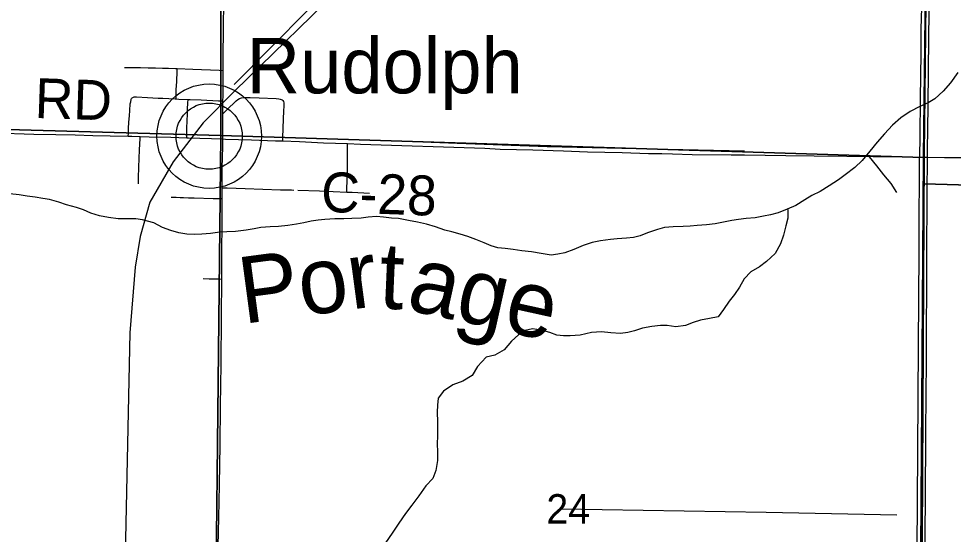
# Model space of a CAD drawing. Extents: x 0 to 39.4, y 0 to 22.
# Drawn here: x 4.106 to 5.438, y 17.856 to 18.59 of the extents above; entities that cross this region are included whole.
import ezdxf

# ---------------------------------------------------------------- set-up
doc = ezdxf.new("R2010")
doc.units = 0
for name, color, linetype in [('GM_X_County_Road', 7, 'Continuous'), ('GM_X_County_Road_Text', 7, 'Continuous'), ('GM_X_Interstate_Route', 7, 'Continuous'), ('GM_X_Major_River', 7, 'Continuous'), ('GM_X_Major_River_Text', 7, 'Continuous'), ('GM_X_Minor_River', 7, 'Continuous'), ('GM_X_Rail_Line', 7, 'Continuous'), ('GM_X_Section', 7, 'Continuous'), ('GM_X_Section_Text', 7, 'Continuous'), ('GM_X_State_Route', 7, 'Continuous'), ('GM_X_Township_Road', 7, 'Continuous'), ('GM_X_Unincorporated', 7, 'Continuous'), ('GM_X_Unincorporated_Location', 7, 'Continuous'), ('GM_X_Unincorporated_Text', 7, 'Continuous')]:
    doc.layers.add(name, color=color, linetype=linetype)

msp = doc.modelspace()

# ---------------------------------------------------------------- linework, layer by layer
at = {"layer": 'GM_X_County_Road'}
for p, q in [((5.3898, 18.3932), (5.3952, 18.3932)), ((5.3952, 18.3932), (5.4008, 18.3931))]:
    msp.add_line(p, q, dxfattribs=at)
for points in [[(3.3797, 18.4462), (3.4197, 18.4448), (3.4663, 18.4434), (3.5378, 18.442), (3.5968, 18.4411), (3.6527, 18.4402), (3.6683, 18.4398), (3.6869, 18.4394), (3.7086, 18.439), (3.7117, 18.4389), (3.7211, 18.4386), (3.7646, 18.4375), (3.864, 18.4344), (3.9292, 18.4325), (3.982, 18.4306), (4.0721, 18.4275), (4.128, 18.4259), (4.1591, 18.4251), (4.187, 18.4246), (4.2119, 18.424), (4.2366, 18.4232), (4.2624, 18.4228)], [(4.2624, 18.4228), (4.2674, 18.4227), (4.2796, 18.4224)], [(4.2796, 18.4224), (4.2922, 18.4221), (4.3233, 18.4213), (4.3457, 18.4205)], [(4.3457, 18.4205), (4.3481, 18.4204), (4.3972, 18.4189)], [(4.3972, 18.4189), (4.4009, 18.4188), (4.4382, 18.4177), (4.4723, 18.4164), (4.4821, 18.4161)], [(4.4821, 18.4161), (4.5065, 18.4153), (4.5406, 18.4136), (4.5748, 18.4123)], [(4.5748, 18.4123), (4.5934, 18.4115), (4.7704, 18.4056), (4.7921, 18.4045), (4.8388, 18.4033), (4.8822, 18.4018), (4.9164, 18.4007), (4.9412, 18.4), (4.9661, 18.3994), (5.0034, 18.3983), (5.0227, 18.398), (5.0376, 18.3977), (5.0655, 18.3969), (5.1214, 18.3964), (5.1401, 18.3964), (5.1991, 18.3955), (5.2395, 18.3948), (5.2861, 18.3944), (5.3234, 18.3938), (5.37, 18.3933), (5.3898, 18.3932)], [(5.4008, 18.3931), (5.4252, 18.3927), (5.4594, 18.3926)]]:
    msp.add_lwpolyline(points, dxfattribs=at)
at = {"layer": 'GM_X_Interstate_Route'}
for points in [[(5.3867, 16.794), (5.3887, 17.3876), (5.3908, 17.7563), (5.3909, 17.7629), (5.395, 18.3937), (5.4055, 19.2651), (5.4066, 19.3573), (5.4067, 19.4006), (5.4136, 19.9268)], [(5.4136, 19.9268), (5.4067, 19.4006), (5.4066, 19.3573), (5.4055, 19.2651), (5.395, 18.3937), (5.3909, 17.7629), (5.3908, 17.7563), (5.3887, 17.3876), (5.3867, 16.794)]]:
    msp.add_lwpolyline(points, dxfattribs=at)
at = {"layer": 'GM_X_Major_River'}
for points in [[(5.444, 18.5134), (5.4337, 18.499), (5.4234, 18.4869), (5.4112, 18.4763), (5.4017, 18.4702), (5.3899, 18.4653), (5.3763, 18.4581), (5.363, 18.4491), (5.3512, 18.4385), (5.3397, 18.4263), (5.3291, 18.4142), (5.3188, 18.4017), (5.3078, 18.3881), (5.2975, 18.3782), (5.2834, 18.368), (5.2739, 18.3608), (5.261, 18.3521), (5.2481, 18.3442), (5.2359, 18.3385), (5.2264, 18.3321), (5.2135, 18.3241), (5.2009, 18.3189), (5.1884, 18.3139), (5.1774, 18.3109), (5.1671, 18.3087), (5.1554, 18.3064), (5.1428, 18.3057), (5.1315, 18.3042), (5.122, 18.3027), (5.1079, 18.2998), (5.0984, 18.2979), (5.0859, 18.2968), (5.073, 18.2957), (5.0628, 18.2949), (5.0529, 18.2942), (5.0388, 18.2935), (5.0263, 18.2928), (5.0165, 18.2901), (5.002, 18.2852), (4.9918, 18.2807), (4.9819, 18.2785), (4.972, 18.2777), (4.9587, 18.2766), (4.9493, 18.2759), (4.9352, 18.274), (4.9231, 18.2714), (4.9105, 18.2669), (4.8972, 18.2612), (4.8843, 18.2567), (4.8744, 18.2548), (4.865, 18.2534), (4.8505, 18.2557), (4.8369, 18.258), (4.8232, 18.2596), (4.8107, 18.2615), (4.7993, 18.2627), (4.7891, 18.2638), (4.7796, 18.2665), (4.7694, 18.2707), (4.7577, 18.2757), (4.7459, 18.2799), (4.7353, 18.2834), (4.7235, 18.2864), (4.7133, 18.2891), (4.7, 18.2937), (4.6872, 18.2976), (4.6743, 18.3003), (4.6617, 18.3026), (4.6473, 18.3057), (4.6375, 18.3061), (4.6261, 18.3076), (4.6159, 18.3084), (4.6041, 18.3077), (4.5942, 18.3062), (4.5809, 18.3055), (4.5696, 18.3051), (4.5567, 18.3052), (4.5426, 18.3044), (4.5331, 18.3033), (4.5229, 18.3018), (4.5126, 18.2996), (4.502, 18.2973), (4.4899, 18.2955), (4.4766, 18.2944), (4.4648, 18.2937), (4.4515, 18.2926), (4.4417, 18.2911), (4.4303, 18.2892), (4.4151, 18.2873), (4.403, 18.2866), (4.3931, 18.2859), (4.3798, 18.2844), (4.3673, 18.2833)], [(4.3673, 18.2833), (4.3563, 18.2826), (4.346, 18.2834), (4.3347, 18.2853), (4.3229, 18.2884), (4.3112, 18.2926), (4.2987, 18.2995), (4.2827, 18.3037), (4.2733, 18.3049), (4.2611, 18.3049), (4.2482, 18.3053), (4.2342, 18.3069), (4.2213, 18.3096), (4.2092, 18.3134), (4.1986, 18.318), (4.1887, 18.3214), (4.1743, 18.3253), (4.1633, 18.3287), (4.1504, 18.3326), (4.1406, 18.3341), (4.1299, 18.336), (4.1182, 18.3376), (4.1068, 18.3392), (4.0939, 18.3407)]]:
    msp.add_lwpolyline(points, dxfattribs=at)
at = {"layer": 'GM_X_Minor_River'}
for points in [[(5.1261, 18.645), (4.5703, 18.6557), (4.4131, 18.4963)], [(4.6325, 18.4166), (4.7308, 18.4129), (4.859, 18.4084), (5.0081, 18.4049), (5.1401, 18.4018)], [(5.3176, 18.3933), (5.3282, 18.3804), (5.3384, 18.3678), (5.3486, 18.3556), (5.3569, 18.3427)], [(5.2021, 18.3185), (5.202, 18.3063), (5.199, 18.2953), (5.1959, 18.282), (5.1913, 18.2695), (5.1837, 18.2558), (5.1715, 18.2441), (5.1616, 18.2369), (5.1491, 18.2294), (5.1399, 18.2195), (5.1331, 18.2077), (5.1258, 18.1975), (5.1182, 18.1877), (5.1102, 18.1759), (5.1026, 18.1657), (5.0904, 18.163), (5.0775, 18.1608), (5.0669, 18.1574), (5.0562, 18.1533), (5.0426, 18.1514), (5.0301, 18.153), (5.0206, 18.153), (5.0081, 18.1515), (4.9951, 18.1493), (4.9834, 18.1455), (4.9739, 18.1433), (4.9636, 18.1418), (4.9496, 18.1426), (4.9367, 18.1441), (4.9223, 18.143), (4.9063, 18.1396), (4.8919, 18.1386), (4.8824, 18.1382), (4.873, 18.1394), (4.8631, 18.1432), (4.8506, 18.1467), (4.8381, 18.1482), (4.8278, 18.146), (4.8183, 18.1399), (4.8084, 18.1308), (4.7978, 18.1183), (4.7848, 18.1108), (4.7723, 18.1078), (4.7598, 18.0949), (4.7521, 18.082), (4.7388, 18.074), (4.7248, 18.0688), (4.7115, 18.0597), (4.7038, 18.0498), (4.7027, 18.0396), (4.7026, 18.0297), (4.703, 18.016), (4.7029, 17.9951), (4.7025, 17.9853), (4.7028, 17.9723), (4.7028, 17.9606), (4.7005, 17.9465), (4.6963, 17.9351), (4.6864, 17.9249), (4.6765, 17.9105), (4.6662, 17.8972), (4.6574, 17.8851), (4.6479, 17.8714), (4.6391, 17.8589), (4.6281, 17.8422)], [(5.357, 17.8827), (5.1711, 17.8866), (4.879, 17.8913)]]:
    msp.add_lwpolyline(points, dxfattribs=at)
at = {"layer": 'GM_X_Rail_Line'}
for points in [[(4.9299, 20.9), (4.9207, 20.2492), (4.9136, 19.4102), (4.7206, 18.8553), (4.6861, 18.7801), (4.66, 18.7382), (4.6327, 18.7007), (4.4144, 18.4874), (4.369, 18.4419), (4.3263, 18.3862), (4.2933, 18.3287), (4.2793, 18.2799), (4.2724, 18.2363), (4.2649, 18.1427), (4.2497, 17.419), (4.2467, 16.9177), (4.235, 16.198), (4.2196, 15.6628), (4.2092, 15.5913), (4.1936, 15.4989), (4.1313, 15.1291), (4.1146, 15.0383)], [(5.3695, 15.387), (5.386, 16.3854), (5.3967, 18.3974), (5.4127, 19.8659), (5.4216, 20.4077), (5.4296, 20.9)]]:
    msp.add_lwpolyline(points, dxfattribs=at)
at = {"layer": 'GM_X_Section'}
for points in [[(3.377, 19.4549), (4.394, 19.4215), (4.3942, 18.4237), (3.3817, 18.4522)], [(4.394, 19.4215), (5.4059, 19.4006), (5.4065, 19.3604), (5.3953, 18.3924), (4.3942, 18.4237)], [(5.4065, 19.3604), (6.4302, 19.3208), (6.4032, 18.3261), (5.3956, 18.3552), (5.3953, 18.3924)], [(3.3817, 18.4522), (4.3942, 18.4237), (4.3832, 17.4133), (3.367, 17.4429)], [(4.3942, 18.4237), (5.3953, 18.3924), (5.3956, 18.3552), (5.3882, 17.3864), (4.3832, 17.4133)], [(5.3956, 18.3552), (6.4032, 18.3261), (6.3887, 17.3403), (5.3882, 17.3864)]]:
    msp.add_lwpolyline(points, close=True, dxfattribs=at)
at = {"layer": 'GM_X_State_Route'}
for points in [[(5.3856, 17.7703), (5.3865, 17.9009), (5.387, 17.9755), (5.388, 18.1247), (5.3889, 18.2583), (5.3892, 18.3111), (5.3896, 18.3578), (5.3897, 18.392), (5.3898, 18.3932), (5.3904, 18.423), (5.391, 18.4759), (5.3919, 18.5411), (5.3921, 18.5753), (5.3927, 18.6064)], [(5.3975, 17.8308), (5.3977, 17.8619), (5.3981, 17.9023), (5.3987, 18.0018), (5.3993, 18.1044), (5.3998, 18.2505), (5.4002, 18.3406), (5.4008, 18.3931), (5.4009, 18.4028), (5.4018, 18.465), (5.4025, 18.5178), (5.4032, 18.6018)]]:
    msp.add_lwpolyline(points, dxfattribs=at)
at = {"layer": 'GM_X_Township_Road'}
for p, q in [((4.3973, 18.4545), (4.3973, 18.4731)), ((4.3964, 18.3342), (4.3964, 18.3495))]:
    msp.add_line(p, q, dxfattribs=at)
for points in [[(4.3977, 18.5164), (4.3978, 18.5293), (4.3982, 18.582), (4.3987, 18.6094)], [(4.2573, 18.5206), (4.2667, 18.5205), (4.28, 18.5206), (4.2906, 18.5204), (4.2967, 18.5203), (4.3012, 18.5203), (4.3112, 18.52), (4.3153, 18.5198), (4.3197, 18.5197), (4.3297, 18.5192), (4.3322, 18.5191)], [(4.3307, 18.476), (4.3307, 18.48), (4.3307, 18.4829), (4.3309, 18.4889), (4.3314, 18.501), (4.332, 18.5153), (4.3322, 18.5191)], [(4.3322, 18.5191), (4.3546, 18.5182), (4.392, 18.5167), (4.3977, 18.5164)], [(4.3973, 18.4731), (4.3974, 18.4797), (4.3977, 18.5164)], [(4.2624, 18.4228), (4.2626, 18.4267), (4.2629, 18.4338), (4.2634, 18.443), (4.264, 18.4518), (4.2645, 18.4597), (4.2653, 18.4689), (4.2659, 18.472), (4.2665, 18.475), (4.2668, 18.4757), (4.2672, 18.4764), (4.2677, 18.4771), (4.2682, 18.4775), (4.269, 18.478), (4.2701, 18.4785), (4.271, 18.4787), (4.2723, 18.4789), (4.2743, 18.4788), (4.29, 18.4778), (4.3051, 18.477), (4.3118, 18.4768), (4.3203, 18.4764), (4.3294, 18.4761), (4.3307, 18.476)], [(4.3307, 18.476), (4.3346, 18.4758), (4.3476, 18.4753)], [(4.3457, 18.4205), (4.3459, 18.4275), (4.3461, 18.4346), (4.3465, 18.4444), (4.3468, 18.4546), (4.347, 18.4613), (4.3473, 18.4704), (4.3476, 18.4753)], [(4.3476, 18.4753), (4.3507, 18.4752), (4.3664, 18.4746), (4.3912, 18.4734), (4.3973, 18.4731)], [(4.3973, 18.4545), (4.4029, 18.4602), (4.4159, 18.4733), (4.4183, 18.4752), (4.421, 18.4767), (4.4239, 18.4776), (4.4269, 18.478), (4.43, 18.4781), (4.4362, 18.478), (4.4489, 18.4775), (4.473, 18.4766), (4.477, 18.4763), (4.4789, 18.4758), (4.4803, 18.4753), (4.4816, 18.4746), (4.4827, 18.4736), (4.4835, 18.4721), (4.4838, 18.4706), (4.4839, 18.4674), (4.4838, 18.4643), (4.4836, 18.4602), (4.483, 18.4456), (4.4827, 18.4357), (4.4822, 18.4192), (4.4821, 18.4161)], [(4.3972, 18.4189), (4.3972, 18.4331), (4.3972, 18.4486), (4.3973, 18.4545)], [(4.2769, 18.3552), (4.2771, 18.3637), (4.2776, 18.3788), (4.2785, 18.4034), (4.2795, 18.4196), (4.2796, 18.4224)], [(4.3964, 18.3495), (4.3964, 18.3773), (4.3971, 18.4084), (4.3971, 18.4115), (4.3972, 18.4189)], [(4.5739, 18.3433), (4.574, 18.3485), (4.5745, 18.37), (4.5746, 18.4037), (4.5747, 18.4068), (4.5748, 18.4123)], [(4.3964, 18.3495), (4.4035, 18.3492), (4.4288, 18.3482), (4.4792, 18.3466), (4.495, 18.3462), (4.4981, 18.3461)], [(4.5038, 18.3461), (4.5347, 18.345), (4.5739, 18.3433)], [(4.3235, 18.336), (4.3266, 18.3359), (4.3308, 18.3358), (4.3364, 18.3356), (4.3411, 18.3354), (4.3482, 18.3352), (4.3565, 18.3349), (4.3834, 18.3341), (4.3896, 18.3341), (4.3964, 18.3342)], [(4.3962, 18.2986), (4.3964, 18.3183), (4.3964, 18.3342)], [(4.5739, 18.3433), (4.5812, 18.343), (4.606, 18.3417)], [(4.3957, 18.2193), (4.3958, 18.2624), (4.3961, 18.2935), (4.3962, 18.2986)], [(4.3689, 18.2199), (4.3779, 18.2197), (4.3911, 18.2194), (4.3957, 18.2193)], [(4.3879, 17.4129), (4.3879, 17.4202), (4.3881, 17.5383), (4.3882, 17.5787), (4.3882, 17.6036), (4.3882, 17.6253), (4.388, 17.6657), (4.3883, 17.7248), (4.3888, 17.7496), (4.3896, 17.8025), (4.3909, 17.8584), (4.3917, 17.9019), (4.3922, 17.9268), (4.3932, 17.9827), (4.394, 18.0386), (4.3949, 18.0977), (4.3953, 18.166), (4.3957, 18.2193)]]:
    msp.add_lwpolyline(points, dxfattribs=at)
at = {"layer": 'GM_X_Unincorporated'}
for radius in [0.0744, 0.0472]:
    msp.add_circle((4.3777, 18.4229), radius, dxfattribs=at)
at = {"layer": 'GM_X_Unincorporated_Location'}
msp.add_line((4.3777, 18.4229), (4.3777, 18.4229), dxfattribs=at)

# ---------------------------------------------------------------- texts
at = {"layer": 'GM_X_County_Road_Text'}
for s, rotation, p in [('RD', 358.041, (4.1286, 18.4489)), ('C-28', 357.9398, (4.5363, 18.3153))]:
    msp.add_text(s, height=0.05682, rotation=rotation, dxfattribs=at).set_placement(p)
at = {"layer": 'GM_X_Major_River_Text'}
for s, height, rotation, p in [('t', 0.0947, 357.5811, (4.6185, 18.1775)), ('Por', 0.09474, 7.5816, (4.4264, 18.1554)), ('age', 0.09474, 347.5805, (4.6564, 18.1763))]:
    msp.add_text(s, height=height, rotation=rotation, dxfattribs=at).set_placement(p)
at = {"layer": 'GM_X_Section_Text'}
msp.add_text('24', height=0.04186, rotation=0, dxfattribs=at).set_placement((4.858, 17.871))
at = {"layer": 'GM_X_Unincorporated_Text'}
msp.add_text('Rudolph', height=0.07898, rotation=0, dxfattribs=at).set_placement((4.4309, 18.4839))

doc.saveas('drawing.dxf')
